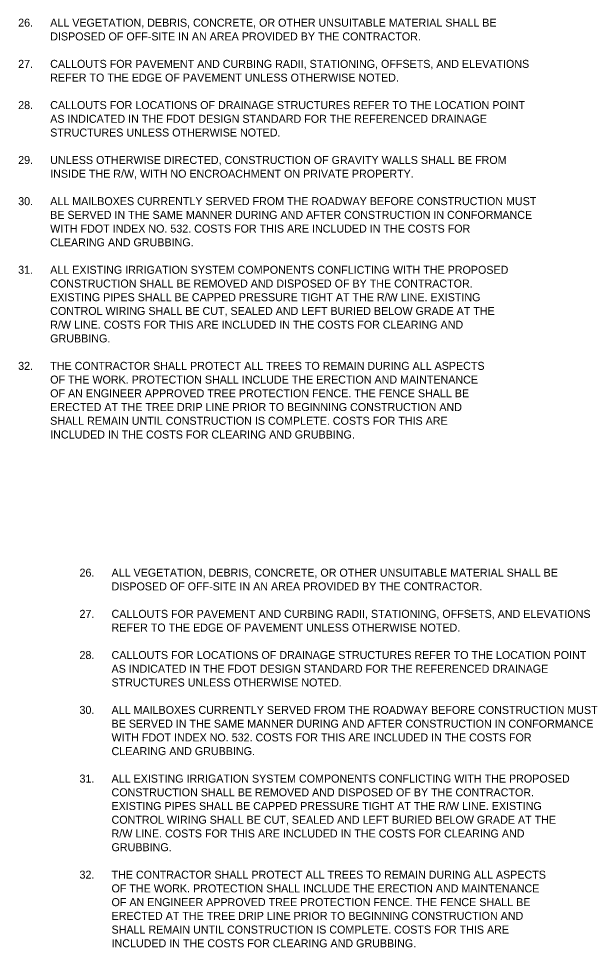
# Model space of a CAD drawing. Extents: x 783907 to 784590, y 832093 to 832609.
# Drawn here: x 784437.6 to 784488.2, y 832400.8 to 832482 of the extents above; entities that cross this region are included whole.
import ezdxf

# ---------------------------------------------------------------- set-up
doc = ezdxf.new("R2010")
doc.units = 0
doc.layers.add('TextLabel', color=7, linetype='Continuous')

msp = doc.modelspace()

# ---------------------------------------------------------------- texts
at = {"layer": 'TextLabel'}
for s, p in [('26.', (784437.612, 832481.323)), ('ALL VEGETATION, DEBRIS, CONCRETE, OR OTHER UNSUITABLE MATERIAL SHALL BE', (784440.412, 832481.323)), ('DISPOSED OF OFF-SITE IN AN AREA PROVIDED BY THE CONTRACTOR.', (784440.412, 832480.123)), ('27.', (784437.612, 832477.723)), ('CALLOUTS FOR PAVEMENT AND CURBING RADII, STATIONING, OFFSETS, AND ELEVATIONS', (784440.412, 832477.723)), ('REFER TO THE EDGE OF PAVEMENT UNLESS OTHERWISE NOTED.', (784440.412, 832476.523)), ('28.', (784437.612, 832474.123)), ('CALLOUTS FOR LOCATIONS OF DRAINAGE STRUCTURES REFER TO THE LOCATION POINT', (784440.412, 832474.123)), ('AS INDICATED IN THE FDOT DESIGN STANDARD FOR THE REFERENCED DRAINAGE', (784440.412, 832472.923)), ('STRUCTURES UNLESS OTHERWISE NOTED.', (784440.412, 832471.723)), ('29.', (784437.612, 832469.323)), ('UNLESS OTHERWISE DIRECTED, CONSTRUCTION OF GRAVITY WALLS SHALL BE FROM', (784440.412, 832469.323)), ('INSIDE THE R/W, WITH NO ENCROACHMENT ON PRIVATE PROPERTY.', (784440.412, 832468.123)), ('30.', (784437.612, 832465.723)), ('ALL MAILBOXES CURRENTLY SERVED FROM THE ROADWAY BEFORE CONSTRUCTION MUST', (784440.412, 832465.723)), ('BE SERVED IN THE SAME MANNER DURING AND AFTER CONSTRUCTION IN CONFORMANCE', (784440.412, 832464.523)), ('WITH FDOT INDEX NO. 532. COSTS FOR THIS ARE INCLUDED IN THE COSTS FOR ', (784440.412, 832463.323)), ('CLEARING AND GRUBBING.', (784440.412, 832462.123)), ('31.', (784437.612, 832459.723)), ('ALL EXISTING IRRIGATION SYSTEM COMPONENTS CONFLICTING WITH THE PROPOSED', (784440.412, 832459.723)), ('CONSTRUCTION SHALL BE REMOVED AND DISPOSED OF BY THE CONTRACTOR. ', (784440.412, 832458.523)), ('EXISTING PIPES SHALL BE CAPPED PRESSURE TIGHT AT THE R/W LINE. EXISTING', (784440.412, 832457.323)), ('CONTROL WIRING SHALL BE CUT, SEALED AND LEFT BURIED BELOW GRADE AT THE', (784440.412, 832456.123)), ('R/W LINE. COSTS FOR THIS ARE INCLUDED IN THE COSTS FOR CLEARING AND ', (784440.412, 832454.923)), ('GRUBBING.', (784440.412, 832453.723)), ('32.', (784437.612, 832451.323)), ('THE CONTRACTOR SHALL PROTECT ALL TREES TO REMAIN DURING ALL ASPECTS', (784440.412, 832451.323)), ('OF THE WORK. PROTECTION SHALL INCLUDE THE ERECTION AND MAINTENANCE ', (784440.412, 832450.123)), ('OF AN ENGINEER APPROVED TREE PROTECTION FENCE. THE FENCE SHALL BE', (784440.412, 832448.923)), ('ERECTED AT THE TREE DRIP LINE PRIOR TO BEGINNING CONSTRUCTION AND', (784440.412, 832447.723)), ('SHALL REMAIN UNTIL CONSTRUCTION IS COMPLETE. COSTS FOR THIS ARE ', (784440.412, 832446.523)), ('INCLUDED IN THE COSTS FOR CLEARING AND GRUBBING.', (784440.412, 832445.323)), ('26.', (784442.973, 832433.244)), ('ALL VEGETATION, DEBRIS, CONCRETE, OR OTHER UNSUITABLE MATERIAL SHALL BE', (784445.773, 832433.244)), ('DISPOSED OF OFF-SITE IN AN AREA PROVIDED BY THE CONTRACTOR.', (784445.773, 832432.044)), ('27.', (784442.973, 832429.644)), ('CALLOUTS FOR PAVEMENT AND CURBING RADII, STATIONING, OFFSETS, AND ELEVATIONS', (784445.773, 832429.644)), ('REFER TO THE EDGE OF PAVEMENT UNLESS OTHERWISE NOTED.', (784445.773, 832428.444)), ('28.', (784442.973, 832426.044)), ('CALLOUTS FOR LOCATIONS OF DRAINAGE STRUCTURES REFER TO THE LOCATION POINT', (784445.773, 832426.044)), ('AS INDICATED IN THE FDOT DESIGN STANDARD FOR THE REFERENCED DRAINAGE', (784445.773, 832424.844)), ('STRUCTURES UNLESS OTHERWISE NOTED.', (784445.773, 832423.644)), ('30.', (784442.973, 832421.244)), ('ALL MAILBOXES CURRENTLY SERVED FROM THE ROADWAY BEFORE CONSTRUCTION MUST', (784445.773, 832421.244)), ('BE SERVED IN THE SAME MANNER DURING AND AFTER CONSTRUCTION IN CONFORMANCE', (784445.773, 832420.044)), ('WITH FDOT INDEX NO. 532. COSTS FOR THIS ARE INCLUDED IN THE COSTS FOR ', (784445.773, 832418.844)), ('CLEARING AND GRUBBING.', (784445.773, 832417.644)), ('31.', (784442.973, 832415.244)), ('ALL EXISTING IRRIGATION SYSTEM COMPONENTS CONFLICTING WITH THE PROPOSED', (784445.773, 832415.244)), ('CONSTRUCTION SHALL BE REMOVED AND DISPOSED OF BY THE CONTRACTOR. ', (784445.773, 832414.044)), ('EXISTING PIPES SHALL BE CAPPED PRESSURE TIGHT AT THE R/W LINE. EXISTING', (784445.773, 832412.844)), ('CONTROL WIRING SHALL BE CUT, SEALED AND LEFT BURIED BELOW GRADE AT THE', (784445.773, 832411.644)), ('R/W LINE. COSTS FOR THIS ARE INCLUDED IN THE COSTS FOR CLEARING AND ', (784445.773, 832410.444)), ('GRUBBING.', (784445.773, 832409.244)), ('32.', (784442.973, 832406.844)), ('THE CONTRACTOR SHALL PROTECT ALL TREES TO REMAIN DURING ALL ASPECTS', (784445.773, 832406.844)), ('OF THE WORK. PROTECTION SHALL INCLUDE THE ERECTION AND MAINTENANCE ', (784445.773, 832405.644)), ('OF AN ENGINEER APPROVED TREE PROTECTION FENCE. THE FENCE SHALL BE', (784445.773, 832404.444)), ('ERECTED AT THE TREE DRIP LINE PRIOR TO BEGINNING CONSTRUCTION AND', (784445.773, 832403.244)), ('SHALL REMAIN UNTIL CONSTRUCTION IS COMPLETE. COSTS FOR THIS ARE ', (784445.773, 832402.044)), ('INCLUDED IN THE COSTS FOR CLEARING AND GRUBBING.', (784445.773, 832400.844))]:
    msp.add_text(s, height=0.7, dxfattribs=at).set_placement(p)

doc.saveas('drawing.dxf')
